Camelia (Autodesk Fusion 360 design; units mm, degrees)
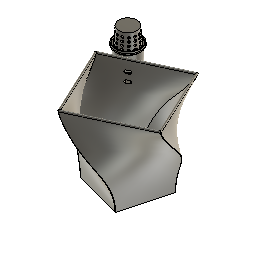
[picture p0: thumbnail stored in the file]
parameter "wall" = 1.35
parameter "height" = 105 (= "Size * 0.75") comment "Vase Hight (Medium setting)"
parameter "tolerance" = 0.15
sketch "Sketch1" plane through (0, 0, 0) normal (0, 0, 1) x axis (1, 0, 0)
  line L1 (-69.0872, -69.0872) -> (69.0872, -69.0872)
  line L2 (-69.0872, 69.0872) -> (-69.0872, -69.0872)
  line L3 (69.0872, 69.0872) -> (-69.0872, 69.0872)
  line L4 (69.0872, -69.0872) -> (69.0872, 69.0872)
  line L5 (-69.0872, 69.0872) -> (69.0872, -69.0872)
  line L6 (69.0872, 69.0872) -> (-69.0872, -69.0872)
  line L7 (-65.5517, 72.6227) -> (72.6227, -65.5517)
  line L8 (-72.6227, 65.5517) -> (65.5517, -72.6227)
  line L9 (-23.3128, 39.7107) -> (37.8852, 23.3128)
  line L10 (-39.7107, -21.4872) -> (-23.3128, 39.7107)
  line L11 (21.4872, -37.8852) -> (-39.7107, -21.4872)
  line L12 (37.8852, 23.3128) -> (21.4872, -37.8852)
  line L13 (-39.7107, -21.4872) -> (37.8852, 23.3128)
  line L14 (21.4872, -37.8852) -> (-23.3128, 39.7107)
  line L15 (-0.9128, 69.0872) -> (-0.9128, 0.9128)
  line L16 (2.6227, 4.4483) -> (-4.4483, -2.6227)
  line L17 (-50.5517, 57.6227) -> (-57.6227, 50.5517)
  circle C1 centre (-0.9128, 0.9128) radius 70
  circle C2 centre (-54.0872, 54.0872) radius 15
  circle C3 centre (-0.9128, 0.9128) radius 44.8
  circle C4 centre (-54.0872, 54.0872) radius 13.65
  circle C5 centre (-54.0872, 54.0872) radius 13.5
  circle C6 centre (-0.9128, 0.9128) radius 60.2
  point P6 (0, 0)
  point P1 (0, 0)
  point P7 (-0.9128, 0.9128)
  point P8 (-54.0872, 54.0872)
  point P9 (-0.9128, 0.9128)
  point P19 (-0.9128, 0.9128)
  point P15 (37.8852, 23.3128)
  point P20 (-0.9128, 0.9128)
  point P21 (-0.9128, 69.0872)
  point P22 (-4.4483, -2.6227)
  point P23 (2.6227, 4.4483)
  point P26 (-0.9128, 0.9128)
  point P27 (-57.6227, 50.5517)
  point P28 (-50.5517, 57.6227)
  point P24 (-54.0872, 54.0872)
  horizontal L1
  perpendicular L1 L2
  parallel L1 L3
  parallel L2 L4
  coincident L5 P6
  coincident L6 P6
  coincident P1 P6
  coincident L5 P7
  coincident L5 P8
  tangent L3 C2
  tangent L4 C1
  coincident P7 P9
  perpendicular L9 L10
  parallel L9 L11
  parallel L10 L12
  coincident L13 P19
  coincident L14 P19
  coincident P9 P19
  equal L9 L12
  coincident C3 P15
  coincident P9 P20
  coincident L3 P21
  perpendicular L3 L15
  coincident L8 P22
  coincident L7 P23
  perpendicular L7 L16
  equal L2 L3
  midpoint P19 L16
  coincident P19 P26
  tangent C2 C6
  coincident L8 P27
  coincident L7 P28
  perpendicular L7 L17
  coincident P24 L17
  dimension "Size" diameter C1 = 140
  dimension "d5" diameter C2 = 30
  dimension "d8" = 5
  dimension "d9" = -5
  dimension "d16" = -25.2 (= "-Size * 0.18")
  dimension "d17" angle L13 L15 = 60
  dimension "d81" distance P7 P8 = 75.2 (= "Size * 0.46 + ( wall * 8 )")
work_plane "WorkPlane1" AlongDistance 70 (= "height / 1.5")
work_plane "WorkPlane2" AlongDistance 105 (= "height")
work_plane "WorkPlane5" AlongDistance 63 (= "height * 0.6")
work_plane "WorkPlane4" RotateAngle 90
sketch "Sketch2" plane through (0, 0, 70) normal (0, 0, 1) x axis (1, 0, 0)
  line L1 (-0.9128, 70.9128) -> (-0.9128, 0.9128)
  line L2 (-0.9128, 63.9128) -> (62.0872, 0.9128)
  line L3 (-63.9128, 0.9128) -> (-0.9128, 63.9128)
  line L4 (-0.9128, -62.0872) -> (-63.9128, 0.9128)
  line L5 (62.0872, 0.9128) -> (-0.9128, -62.0872)
  line L6 (-63.9128, 0.9128) -> (62.0872, 0.9128)
  line L7 (-0.9128, -62.0872) -> (-0.9128, 63.9128)
  circle C1 centre (-0.9128, 0.9128) radius 70
  circle C2 centre (-0.9128, 0.9128) radius 63
  point P2 (-0.9128, 0.9128)
  point P4 (-0.9128, 0.9128)
  point P5 (-0.9128, 70.9128)
  point P10 (-0.9128, 0.9128)
  point P6 (62.0872, 0.9128)
  coincident P2 P4
  coincident C1 P5
  vertical L1
  perpendicular L2 L3
  parallel L2 L4
  parallel L3 L5
  coincident L6 P10
  coincident L7 P10
  coincident P2 P10
  equal L2 L5
  coincident C2 P6
  dimension "d14" = -7 (= "-Size * 0.05")
  dimension "d15" angle L1 L6 = 90
sketch "Sketch3" plane through (0, 0, 105) normal (0, 0, 1) x axis (1, 0, 0)
  line L1 (23.0286, 66.6913) -> (64.8657, -23.0286)
  line L2 (-66.6913, 24.8542) -> (23.0286, 66.6913)
  line L3 (-24.8542, -64.8657) -> (-66.6913, 24.8542)
  line L4 (64.8657, -23.0286) -> (-24.8542, -64.8657)
  line L5 (-66.6913, 24.8542) -> (64.8657, -23.0286)
  line L6 (-24.8542, -64.8657) -> (23.0286, 66.6913)
  line L7 (-0.9128, 70.9128) -> (-0.9128, 0.9128)
  circle C1 centre (-0.9128, 0.9128) radius 70
  circle C2 centre (-54.0872, 54.0872) radius 15
  circle C3 centre (-54.0872, 54.0872) radius 7.5
  point P7 (-0.9128, 0.9128)
  point P2 (-0.9128, 0.9128)
  point P3 (64.8657, -23.0286)
  point P8 (-0.9128, 0.9128)
  point P9 (-0.9128, 70.9128)
  perpendicular L1 L2
  parallel L1 L3
  parallel L2 L4
  coincident L5 P7
  coincident L6 P7
  coincident P2 P7
  equal L1 L4
  coincident C1 P3
  coincident P2 P8
  coincident C1 P9
  vertical L7
  concentric C2 C3
  dimension "d18" angle L5 L7 = 110
  dimension "d126" diameter C3 = 15
sketch "Sketch9" plane through (0, 0, 63) normal (0, 0, 1) x axis (1, 0, 0)
  circle C1 centre (-54.0872, 54.0872) radius 13.65
  circle C2 centre (-54.0872, 54.0872) radius 11
  concentric C1 C2
  dimension "d127" diameter C2 = 22
loft "Loft2" sketch "Sketch1" + "Sketch9" + "Sketch3" Start Weight 4.0298 Start TakeOff Angle 0 End Weight -3.9427 End TakeOff Angle 0
loft "Loft1" sketch "Sketch1" + "Sketch2" + "Sketch3" Start Weight 1.991 Start TakeOff Angle 0 End Weight -1.8239 End TakeOff Angle 0
chamfer "Chamfer4" distance 0.5
extrude "Extrude2" new body sketch "Sketch1" profile of C1 C2 L7 L8 C3 L9 L10 L16 C4 C5 C6 L17 blind 15 from offset 3
extrude "Extrude3" sketch "Sketch1" profile of C1 C2 L7 L8 C3 L9 L10 L16 C4 C5 C6 L17 blind -15 from offset -10
chamfer "Chamfer1" distance 1.35 (= "wall")
fillet "Fillet1" radius 3
extrude "Extrude17" sketch "Sketch1" profile of C1 L7 L8 C5 blind 20 taper -5
shell "Shell1" innerThickness 1.35 (= "wall")
extrude "Extrude18" add sketch "Sketch1" profile of C1 C2 L7 L8 C4 C5 along normal blind 20 taper -3
extrude "Extrude16" cut sketch "Sketch1" profile of C1 L7 L8 C4 C5 along normal blind 20 taper -5
offset_faces "OffsetFaces5" distance 1.35 (= "wall")
sketch "Sketch6" plane through (0, 0, 105) normal (0, 0, 1) x axis (-1, 0, 0)
  line L1 (54.0872, -37.5872) -> (54.0872, -70.5872)
  line L2 (46.4193, -39.4772) -> (61.7551, -68.6972)
  line L3 (40.508, -44.7141) -> (67.6664, -63.4603)
  line L4 (37.7075, -52.0984) -> (70.4669, -56.0761)
  line L5 (38.6594, -59.9382) -> (69.515, -48.2362)
  line L6 (43.1457, -66.4376) -> (65.0287, -41.7368)
  line L7 (50.1385, -70.1078) -> (58.0359, -38.0667)
  line L8 (58.0359, -70.1078) -> (50.1385, -38.0667)
  line L9 (65.0287, -66.4376) -> (43.1457, -41.7368)
  line L10 (69.515, -59.9382) -> (38.6594, -48.2362)
  line L11 (70.4669, -52.0984) -> (37.7075, -56.0761)
  line L12 (67.6664, -44.7141) -> (40.508, -63.4603)
  line L13 (61.7551, -39.4772) -> (46.4193, -68.6972)
  circle C1 centre (54.0872, -54.0872) radius 15.15
  circle C2 centre (54.0872, -54.0872) radius 16.5
  circle C3 centre (54.0872, -54.0872) radius 12.3
  circle C4 centre (54.0872, -54.0872) radius 15
  circle C5 centre (54.0872, -54.0872) radius 13.65
  point P5 (54.0872, -70.5872)
  point P6 (54.0872, -37.5872)
  point P3 (54.0872, -54.0872)
  coincident C2 P5
  coincident C2 P6
  vertical L1
  coincident P3 L1
  concentric C2 C4
  concentric C3 C5
  dimension "d115" distance C1 C2 = 1.35 (= "wall")
  dimension "d140" distance C1 C4 = 0.15 (= "tolerance")
  dimension "d141" distance C3 C5 = 1.35 (= "wall")
  dimension "d74" C-Pattern1-Angle = 360
extrude "Extrude7" add sketch "Sketch6" profile of C1 C2 C3 L1 L2 L3 L4 L5 L6 L7 L8 L9 L10 L11 L12 L13 no distance stored
extrude "Extrude6" add sketch "Sketch6" profile of C1 C2 L1 L2 L3 L4 L5 L6 L7 L8 L9 L10 L11 L12 L13 along normal blind 2 taper -5
extrude "Extrude8" cut sketch "Sketch6" profile of C3 L1 L2 L3 L4 L5 L6 L7 L8 L9 L10 L11 L12 L13 C5 along normal blind 2.5
rectangular_pattern "R-Pattern1" uSpaceDistance 4.5 vSpaceDistance 0
chamfer "Chamfer5" distance 0.8
circular_pattern "C-Pattern1" countU 13 TotalAngle 360
chamfer "Chamfer7" distance 2.7 (= "wall * 2") distance 1.5 (= "wall + tolerance")
sketch "Sketch7" plane through (-0.9128, 0.9128, 0) normal (0.7071, -0.7071, 0) x axis (0.7071, 0.7071, 0)
  line L1 (3.65, 6) -> (3.65, 15)
  line L2 (-3.65, 15) -> (-3.65, 6)
  line L3 (5, 15) -> (5, 6)
  line L4 (-5, 6) -> (-5, 15)
  line L5 (-3.65, 92) -> (-3.65, 83)
  line L6 (3.65, 83) -> (3.65, 92)
  line L7 (5, 92) -> (5, 83)
  line L8 (-5, 83) -> (-5, 92)
  line L9 (-2, 4.35) -> (2, 4.35)
  line L10 (2, 16.65) -> (-2, 16.65)
  line L11 (2, 3) -> (-2, 3)
  line L12 (-2, 18) -> (2, 18)
  line L13 (-2, 81.35) -> (2, 81.35)
  line L14 (2, 93.65) -> (-2, 93.65)
  line L15 (-2, 95) -> (2, 95)
  line L16 (2, 80) -> (-2, 80)
  line L17 (2, 83) -> (-2, 92)
  line L18 (2, 6) -> (-2, 15)
  line L19 (2, 90.35) -> (-2, 90.35)
  line L20 (2, 84.65) -> (-2, 84.65)
  line L21 (2, 13.35) -> (-2, 13.35)
  line L22 (2, 7.65) -> (-2, 7.65)
  arc A1 centre (-2, 6) radius 1.65 clockwise from (-2, 4.35) to (-3.65, 6)
  arc A2 centre (-2, 15) radius 1.65 clockwise from (-3.65, 15) to (-2, 16.65)
  arc A3 centre (-2, 6) radius 3 clockwise from (-2, 3) to (-5, 6)
  arc A4 centre (-2, 15) radius 3 clockwise from (-5, 15) to (-2, 18)
  arc A5 centre (2, 83) radius 1.65 clockwise from (3.65, 83) to (2, 81.35)
  arc A6 centre (2, 92) radius 1.65 clockwise from (2, 93.65) to (3.65, 92)
  arc A7 centre (2, 83) radius 3 clockwise from (5, 83) to (2, 80)
  arc A8 centre (2, 92) radius 3 clockwise from (2, 95) to (5, 92)
  arc A9 centre (2, 6) radius 1.65 clockwise from (3.65, 6) to (2, 4.35)
  arc A10 centre (2, 15) radius 1.65 clockwise from (2, 16.65) to (3.65, 15)
  arc A11 centre (2, 6) radius 3 clockwise from (5, 6) to (2, 3)
  arc A12 centre (2, 15) radius 3 clockwise from (2, 18) to (5, 15)
  arc A13 centre (-2, 83) radius 1.65 clockwise from (-2, 81.35) to (-3.65, 83)
  arc A14 centre (-2, 92) radius 1.65 clockwise from (-3.65, 92) to (-2, 93.65)
  arc A15 centre (-2, 92) radius 3 clockwise from (-5, 92) to (-2, 95)
  arc A16 centre (-2, 83) radius 3 clockwise from (-2, 80) to (-5, 83)
  circle C1 centre (2, 92) radius 1.65
  circle C2 centre (-2, 92) radius 1.65
  circle C3 centre (-2, 83) radius 1.65
  circle C4 centre (2, 83) radius 1.65
  circle C5 centre (0, 87.5) radius 1.65
  circle C6 centre (2, 15) radius 1.65
  circle C7 centre (-2, 15) radius 1.65
  circle C8 centre (-2, 6) radius 1.65
  circle C9 centre (2, 6) radius 1.65
  circle C10 centre (0, 10.5) radius 1.65
  point P39 (-2, 92)
  point P42 (-2, 92)
  point P20 (2, 83)
  point P43 (2, 83)
  point P19 (-2, 15)
  point P44 (-2, 15)
  point P27 (2, 6)
  point P45 (2, 6)
  point P49 (2, 83)
  point P50 (0, 87.5)
  point P52 (-2, 15)
  point P54 (2, 6)
  point P55 (0, 10.5)
  point P56 (-2, 90.35)
  point P57 (2, 90.35)
  point P58 (-2, 84.65)
  point P59 (2, 84.65)
  point P60 (-2, 13.35)
  point P61 (2, 13.35)
  point P62 (-2, 7.65)
  point P63 (2, 7.65)
  point P11 (2, 93.65)
  point P18 (-2, 6)
  point P53 (-2, 6)
  coincident P39 P42
  coincident P20 P43
  coincident P19 P44
  coincident P27 P45
  concentric A6 C1
  concentric A14 C2
  concentric A13 C3
  coincident P43 P49
  midpoint L17 P50
  concentric A10 C6
  coincident P44 P52
  coincident P45 P54
  midpoint L18 P55
  equal C1 C2
  equal C1 C5
  equal C1 C4
  equal C1 C3
  equal C1 C6
  equal C1 C7
  equal C1 C10
  equal C1 C9
  equal C1 C8
  coincident C2 P56
  coincident C1 P57
  tangent C1 L19
  horizontal L19
  coincident C3 P58
  coincident C4 P59
  tangent C4 L20
  parallel L19 L20
  coincident C7 P60
  coincident C6 P61
  tangent C6 L21
  parallel L20 L21
  coincident C8 P62
  coincident C9 P63
  tangent C9 L22
  parallel L21 L22
  coincident P11 C1
  coincident P18 P53
extrude "Extrude19" cut sketch "Sketch7" profile of L1 L2 L5 L6 A1 A2 A5 A6 A9 L9 L10 A10 L13 A13 A14 L14 C1 C2 C3 C4 C5 C6 C7 C8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 against normal blind 75.2 (magnitude of "-d81")
extrude "Extrude14" cut sketch "Sketch7" profile of A1 A2 A5 A6 A9 L9 L10 A10 L13 A13 A14 L14 C1 C2 C3 C4 C6 C7 C8 C9 L19 L20 L21 L22 against normal blind 70 (magnitude of "-Size / 2")
combine "Combine6"
remove_body "RemoveBody21"
remove_body "RemoveBody22"
combine "Combine7"
remove_body "RemoveBody23"
remove_body "RemoveBody24"
sketch "Sketch8" plane through (0, 0, 0) normal (0.7071, 0.7071, 0) x axis (-0.7071, 0.7071, 0)
  line L1 (89.1555, 84.3504) -> (64.5521, 80.0121)
  line L2 (43.0145, 66.35) -> (-12.9297, 66.35)
  line L3 (89.1555, 84.3504) -> (89.1555, 85.7212)
  line L4 (89.1555, 85.7212) -> (64.3652, 81.35)
  curve K1 (89.8076, 20) -> (90.1031, 100.9502)
  curve K2 (64.3652, 81.35) -> (63.1742, 20)
  curve K3 (62.8787, 100.9502) -> (63.1596, 93.65)
  line L5 (48.131, 80) -> (47.5908, 80)
  line L6 (47.8878, 81.35) -> (48.4961, 81.35)
  point P6 (89.1555, 85.7212)
  point P5 (64.3652, 81.35)
  point P10 (64.3652, 81.35)
  point P13 (64.5521, 80.0121)
  point P2 (-12.9297, 66.35)
  horizontal L2
  parallel L1 L4
  vertical L3
  coincident P6 K1
  coincident P5 P10
  coincident K2 P13
  coincident P2 L1
  dimension "d84" angle L1 L2 = 10
  dimension "d136" distance L1 L4 = 1.35 (= "wall")
extrude "Extrude11" new body sketch "Sketch8" profile of L1 L3 L4 distance 20
combine "Combine5"
remove_body "RemoveBody9"
remove_body "RemoveBody14"
work_plane "WorkPlane3" RotateAngle 90
sketch "Sketch5" plane through (-0.9128, 30, 100) normal (1, 0, 0) x axis (0, 1, 0)
  line L1 (24.0376, 5) -> (25.3876, 5)
  line L2 (24.7126, 4.2) -> (24.7126, 5)
  line L3 (-52.3756, 5) -> (34.8972, 5)
  line L4 (36.6913, 5) -> (-53.0286, 5)
  curve K1 (31.704, -29.8091) -> (24.0376, 5)
  circle C1 centre (24.7126, 4.2) radius 1.25
  point P2 (25.3876, 5)
  point P3 (24.0376, 5)
  point P5 (24.7126, 5)
  point P4 (24.7126, 4.2)
  point P6 (24.7126, 4.2)
  point P11 (24.0376, 5)
  coincident P2 L4
  coincident P3 L3
  midpoint L1 P5
  perpendicular L1 L2
  coincident P4 P6
  coincident P3 P11
  dimension "d36" diameter C1 = 2.5
  dimension "d135" distance P5 P6 = 0.8
sweep "Sweep1" sketch "Sketch5" TwistAngle 0 TaperAngle 0
combine "Combine8"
